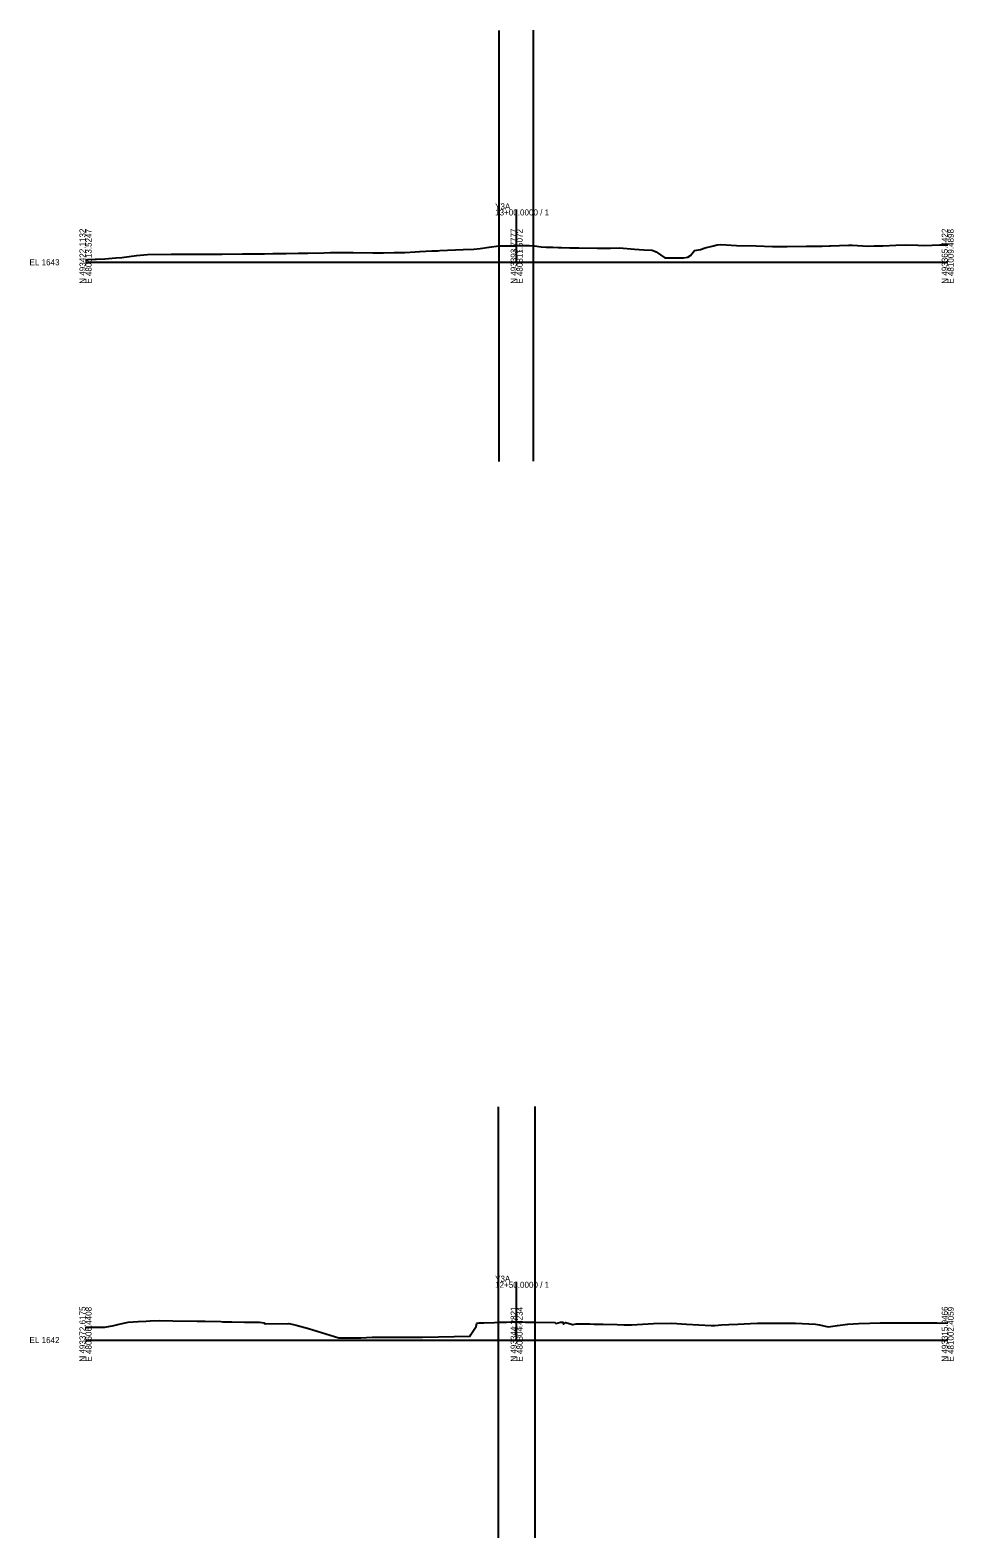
# Model space of a CAD drawing. Extents: x -26 to 403, y -10 to 3108.
# Drawn here: x -26 to 403, y 2408 to 3108 of the extents above; entities that cross this region are included whole.
import ezdxf

# ---------------------------------------------------------------- set-up
doc = ezdxf.new("R2010")
doc.units = 0
for name, color, linetype in [('Exist Cross Section Cell', 7, 'Continuous'), ('Exist XS Center Line Elevation Label', 7, 'Continuous'), ('Exist XS Ground Line', 7, 'Continuous'), ('Scratch_Level_1', 7, 'Continuous')]:
    doc.layers.add(name, color=color, linetype=linetype)

msp = doc.modelspace()

# ---------------------------------------------------------------- linework, layer by layer
at = {"layer": 'Exist Cross Section Cell'}
for p, q in [((200, 3000), (200, 3024.49)), ((0, 3000), (200, 3000)), ((200, 3000), (400, 3000)), ((200, 2500), (200, 2527.05)), ((0, 2500), (200, 2500)), ((200, 2500), (400, 2500))]:
    msp.add_line(p, q, dxfattribs=at)
at = {"layer": 'Exist XS Ground Line'}
for points in [[(0, 3001.18), (0.8, 3001.17), (1.14, 3001.21), (4.49, 3001.4), (5.15, 3001.37), (9, 3001.61), (14.01, 3002.03), (16.9, 3002.24), (23.72, 3003.18), (28.77, 3003.55), (39.74, 3003.75), (42.55, 3003.71), (44.66, 3003.69), (52.66, 3003.72), (59.4, 3003.77), (62.76, 3003.8), (63.32, 3003.8), (72.86, 3003.9), (80.02, 3003.9), (82.97, 3003.95), (86.91, 3003.98), (93.07, 3004.06), (98.7, 3004.13), (103.18, 3004.22), (110.49, 3004.42), (113.59, 3004.44), (115.13, 3004.44), (123.42, 3004.53), (124.24, 3004.53), (133.25, 3004.37), (138.28, 3004.39), (143.11, 3004.48), (148.14, 3004.58), (152.95, 3004.75), (155.16, 3005.03), (160.67, 3005.22), (163.52, 3005.3), (164.43, 3005.4), (175.23, 3005.86), (180.08, 3006.02), (183.09, 3006.31), (187.25, 3006.95), (191.78, 3007.56), (193.03, 3007.55), (193.49, 3007.56), (195.55, 3007.6), (196.44, 3007.62), (198.06, 3007.65), (199.39, 3007.66), (200.02, 3007.67), (200.58, 3007.68), (201.49, 3007.68), (203.1, 3007.69), (203.69, 3007.7), (205.85, 3007.71), (207.7, 3007.65), (208.24, 3007.56), (211.46, 3007.16), (213.78, 3007.03), (215.31, 3006.95), (216.78, 3006.91), (219.2, 3006.82), (220.89, 3006.8), (224.63, 3006.69), (228.9, 3006.63), (237.42, 3006.47), (243.54, 3006.48), (247.66, 3006.6), (254.65, 3006.09), (258.99, 3005.75), (262.88, 3005.64), (264.67, 3004.74), (268.76, 3002.05), (271.33, 3002.04), (273.96, 3002.05), (277.39, 3002.08), (279.41, 3002.29), (280.69, 3003.18), (282.55, 3005.44), (285.35, 3005.94), (287.54, 3006.61), (291.41, 3007.67), (292.96, 3008.12), (294.68, 3008.16), (302.01, 3007.7), (311.2, 3007.56), (318.67, 3007.35), (325.46, 3007.24), (334.53, 3007.39), (335.57, 3007.38), (336.34, 3007.41), (341.78, 3007.52), (345.18, 3007.59), (345.67, 3007.6), (354.02, 3007.89), (355.77, 3007.87), (362.86, 3007.44), (365.88, 3007.57), (369.9, 3007.65), (375.98, 3007.97), (380.54, 3008.14), (386.08, 3007.94), (389.38, 3007.82), (396.19, 3008.04), (398.22, 3008.05), (400, 3008.04)], [(0, 2506), (2.68, 2506), (8.94, 2505.94), (13.14, 2506.82), (15.6, 2507.47), (19.82, 2508.38), (24.44, 2508.66), (28.13, 2508.85), (29.99, 2508.95), (34.24, 2509.02), (40.43, 2508.92), (51.75, 2508.79), (53.43, 2508.76), (55.47, 2508.79), (62.78, 2508.61), (63.65, 2508.55), (67.82, 2508.43), (73.82, 2508.39), (80.7, 2508.25), (82.86, 2507.94), (83.2, 2507.55), (83.51, 2507.77), (93.57, 2507.58), (94.37, 2507.69), (96.56, 2507.27), (97.68, 2506.94), (103.51, 2505.36), (117.51, 2501.08), (125.43, 2501.08), (127.73, 2501.07), (133.01, 2501.3), (142.1, 2501.39), (148.33, 2501.4), (156.29, 2501.41), (178.42, 2501.76), (178.73, 2502.64), (181.25, 2506.36), (181.49, 2507.93), (182.53, 2507.94), (183.02, 2507.94), (184.74, 2507.97), (189.66, 2508.21), (191.39, 2508.27), (191.7, 2508.29), (192.62, 2508.32), (193.78, 2508.34), (195.35, 2508.36), (197.64, 2508.44), (198.82, 2508.44), (200, 2508.45), (200.58, 2508.45), (201.31, 2508.44), (202.69, 2508.41), (204.17, 2508.38), (205.2, 2508.34), (207.04, 2508.32), (207.64, 2508.3), (208.45, 2508.34), (208.84, 2508.34), (217.74, 2508.09), (218.22, 2507.68), (220.35, 2508.3), (221.37, 2508.3), (221.67, 2507.34), (222.82, 2508.15), (225.88, 2507.27), (226.26, 2507.21), (227.55, 2507.54), (228.55, 2507.54), (229.31, 2507.53), (230.12, 2507.51), (234.01, 2507.5), (236.02, 2507.39), (240.08, 2507.35), (246.66, 2507.18), (249.76, 2507.1), (253.32, 2507.08), (260.97, 2507.6), (263.51, 2507.77), (271.99, 2507.82), (278.75, 2507.4), (290.27, 2506.7), (291.95, 2506.79), (295.12, 2507.03), (298.38, 2507.27), (302.56, 2507.47), (308.53, 2507.68), (311.7, 2507.84), (319.49, 2507.93), (326.23, 2507.78), (329.3, 2507.79), (338.58, 2507.45), (340.44, 2507.03), (344.52, 2506.14), (348.79, 2506.76), (353.58, 2507.38), (358.58, 2507.63), (363.82, 2507.8), (368.58, 2508.02), (370.35, 2508.02), (372.47, 2508.03), (377.13, 2508.07), (383.08, 2508.08), (391.69, 2508.05), (395.05, 2507.94), (396.18, 2507.93), (400, 2507.97)]]:
    msp.add_lwpolyline(points, dxfattribs=at)
at = {"layer": 'Scratch_Level_1'}
for p, q in [((191.78, 3107.56), (191.78, 2907.56)), ((207.7, 3107.65), (207.7, 2907.65)), ((191.39, 2608.27), (191.39, 2408.27)), ((208.45, 2608.34), (208.45, 2408.34))]:
    msp.add_line(p, q, dxfattribs=at)

# ---------------------------------------------------------------- texts
at = {"layer": 'Exist Cross Section Cell'}
for s, p in [('Y3A', (190, 3024.49)), ('13+00.0000 / 1', (190, 3021.69)), ('EL 1643', (-26, 2998.6)), ('Y3A', (190, 2527.05)), ('12+50.0000 / 1', (190, 2524.25)), ('EL 1642', (-26, 2498.6))]:
    msp.add_text(s, height=2.8, dxfattribs=at).set_placement(p)
for s, p in [('N 493422.1132', (0, 2990)), ('E 480613.5247', (2.8, 2990)), ('N 493393.7777', (200, 2990)), ('E 480811.5072', (202.8, 2990)), ('N 493365.4422', (400, 2990)), ('E 481009.4898', (402.8, 2990)), ('N 493372.6175', (0, 2490)), ('E 480606.4408', (2.8, 2490)), ('N 493344.2821', (200, 2490)), ('E 480804.4234', (202.8, 2490)), ('N 493315.9466', (400, 2490)), ('E 481002.4059', (402.8, 2490))]:
    msp.add_text(s, height=2.8, rotation=90, dxfattribs=at).set_placement(p)
at = {"layer": 'Exist XS Center Line Elevation Label'}
for s, p in [('1650.67', (197.93, 3004.77)), ('1650.45', (197.88, 2505.55))]:
    msp.add_text(s, height=0.9, dxfattribs=at).set_placement(p)

doc.saveas('drawing.dxf')
